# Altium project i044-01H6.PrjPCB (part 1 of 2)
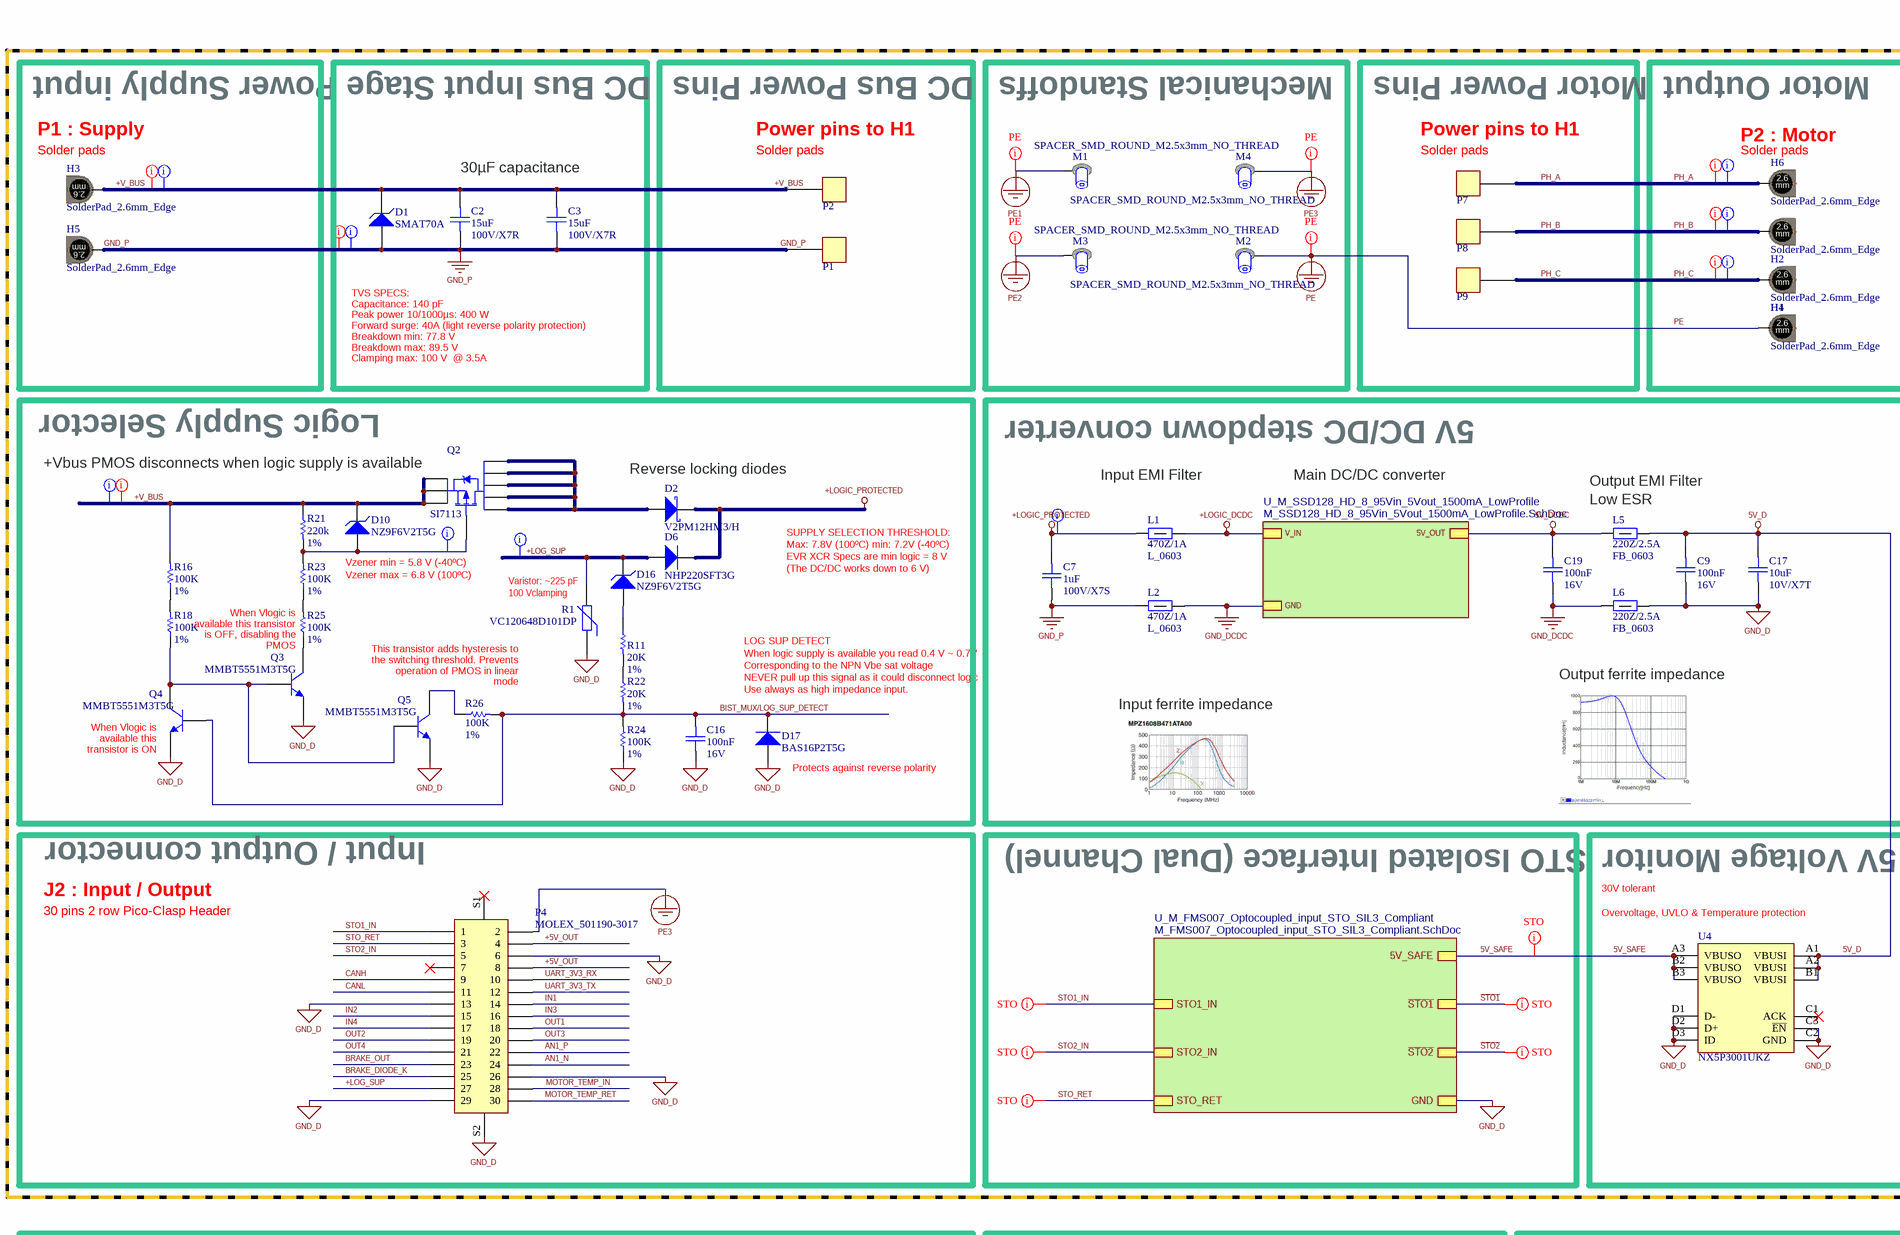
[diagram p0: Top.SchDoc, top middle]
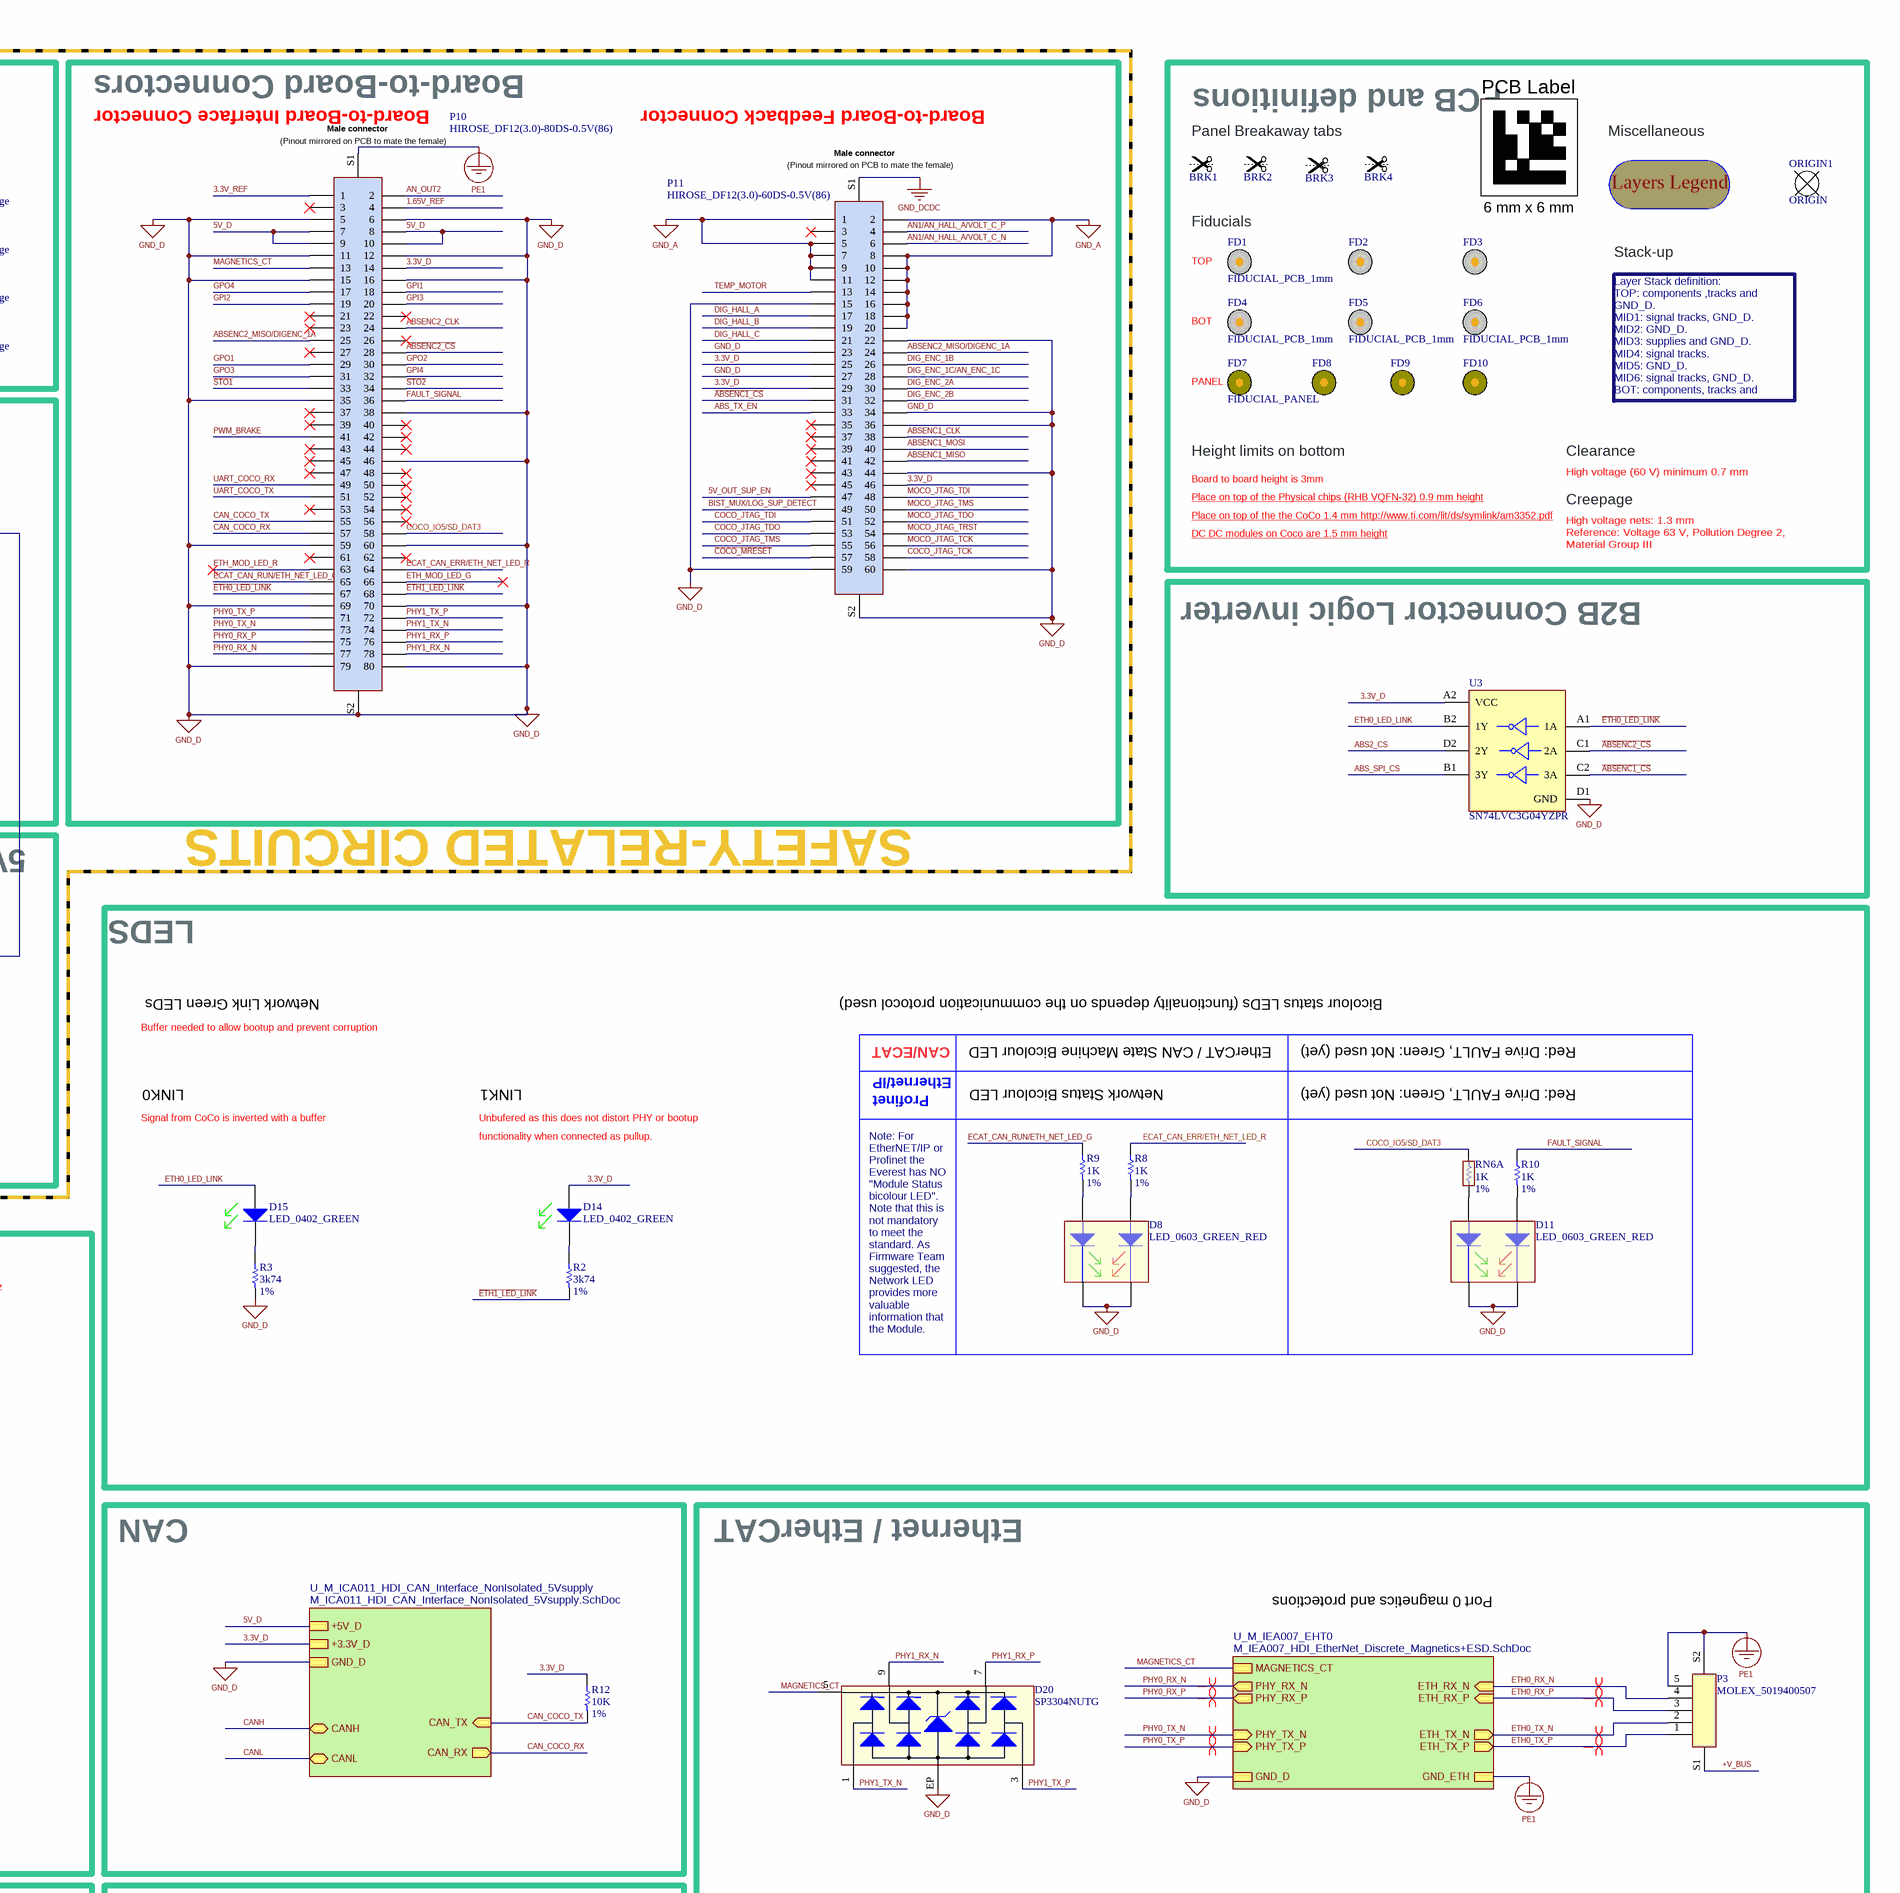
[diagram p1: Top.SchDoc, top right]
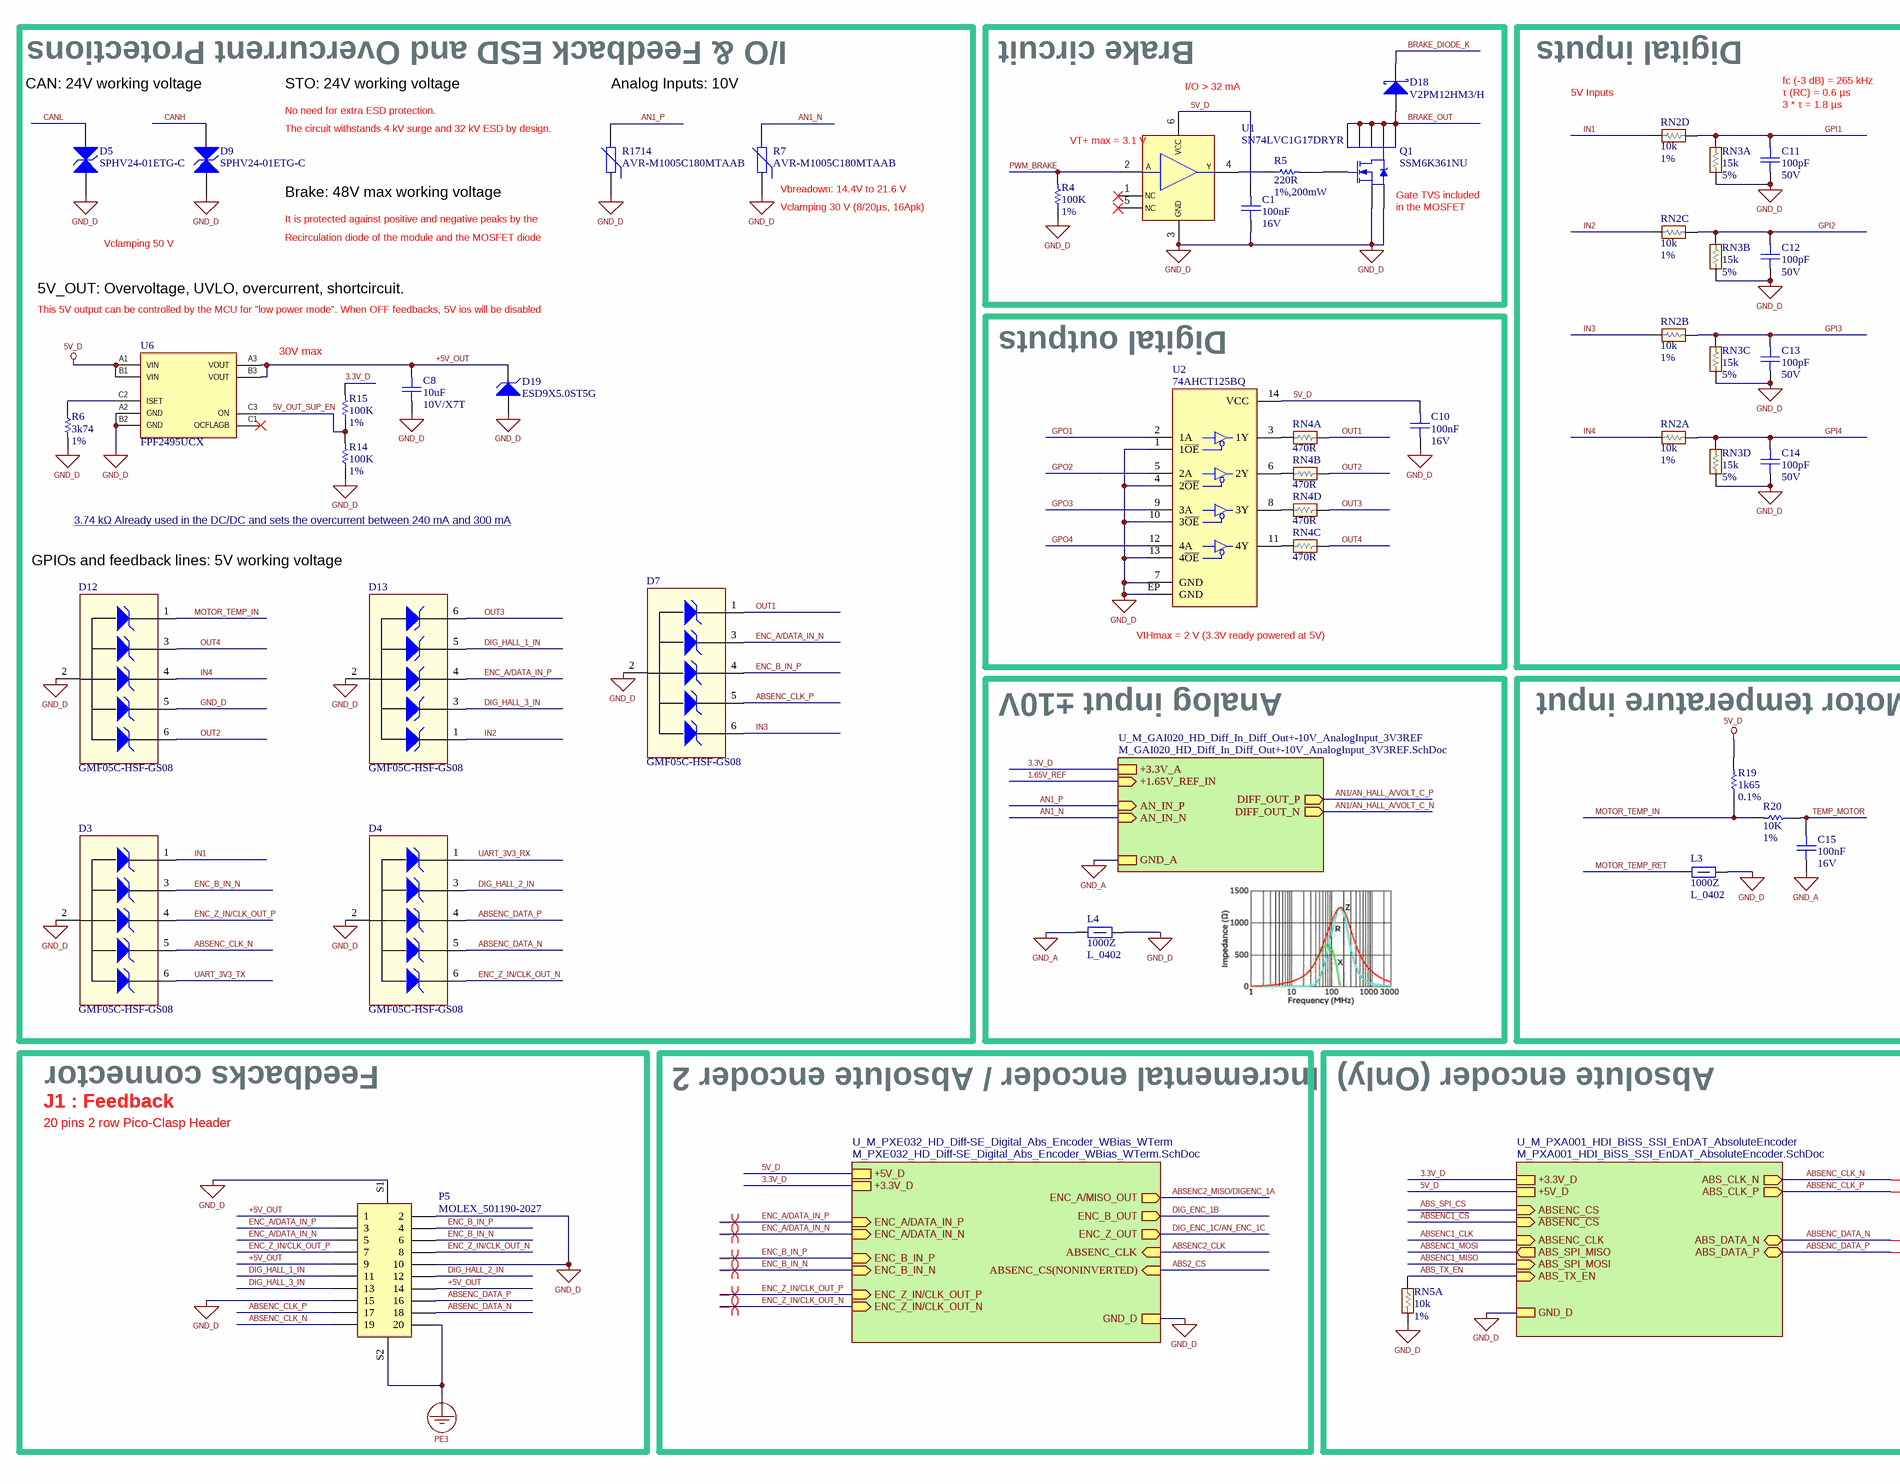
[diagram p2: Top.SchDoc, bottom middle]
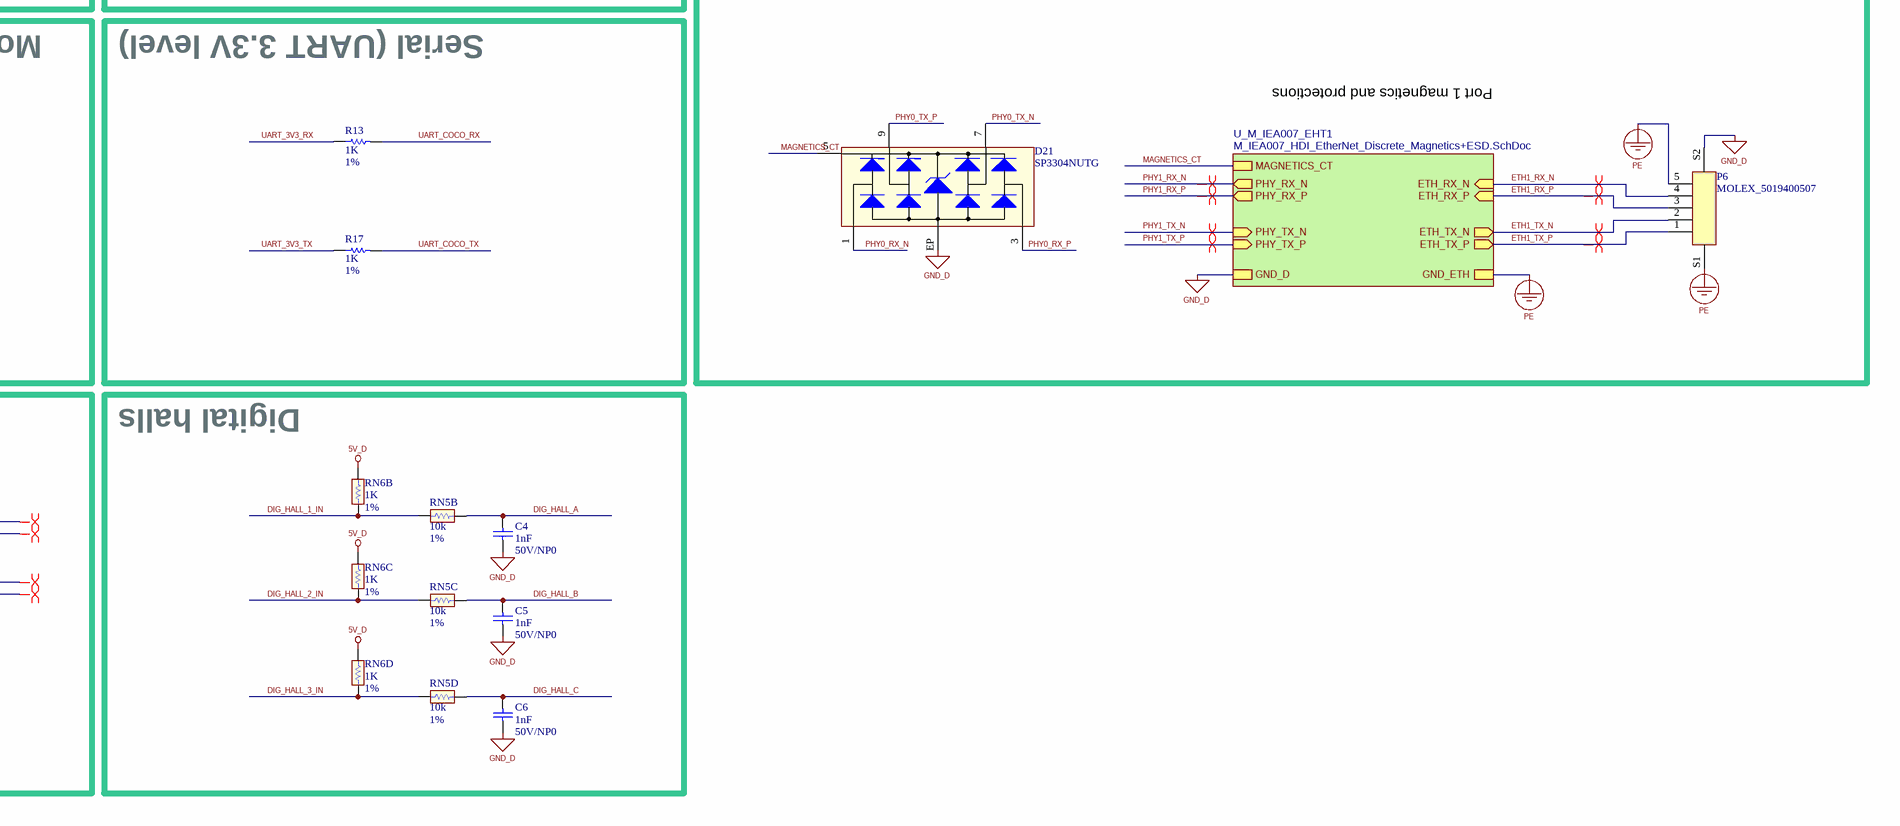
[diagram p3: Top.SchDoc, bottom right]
PCB_Revision: i044-01H6-1.2; ProjectRevision: i044-01H6-1.2.3
8 sheets, 235 parts. Net scope: hierarchical (ports join the sheet entries above them; power ports are global).
Board file: i044-01H6.PcbDoc
Sheets:
  Top.SchDoc
    U_M_SSD128_HD_8_95Vin_5Vout_1500mA_LowProfile = M_SSD128_HD_8_95Vin_5Vout_1500mA_LowProfile.SchDoc
    U_M_ICA011_HDI_CAN_Interface_NonIsolated_5Vsupply = M_ICA011_HDI_CAN_Interface_NonIsolated_5Vsupply.SchDoc
    U_M_PXE032_HD_Diff-SE_Digital_Abs_Encoder_WBias_WTerm = M_PXE032_HD_Diff-SE_Digital_Abs_Encoder_WBias_WTerm.SchDoc
    U_M_IEA007_EHT0 = M_IEA007_HDI_EtherNet_Discrete_Magnetics+ESD.SchDoc
    U_M_IEA007_EHT1 = M_IEA007_HDI_EtherNet_Discrete_Magnetics+ESD.SchDoc
    U_M_PXA001_HDI_BiSS_SSI_EnDAT_AbsoluteEncoder = M_PXA001_HDI_BiSS_SSI_EnDAT_AbsoluteEncoder.SchDoc
    U_M_FMS007_Optocoupled_input_STO_SIL3_Compliant = M_FMS007_Optocoupled_input_STO_SIL3_Compliant.SchDoc
    U_M_GAI020_HD_Diff_In_Diff_Out+-10V_AnalogInput_3V3REF = M_GAI020_HD_Diff_In_Diff_Out+-10V_AnalogInput_3V3REF.SchDoc

## Sheet Top.SchDoc: ixxx
size A1; Organization: Ingenia Drives - Novanta; Address1: Carrer Avila, 124, 2B; Address2: 08018 Barcelona Spain; Address3: www.ingeniamc.com; Address4: www.ingeniamc.com; DocumentNumber: 1; Revision: i044-01H6-1.2.3; SheetNumber: 1; SheetTotal: 8

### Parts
(Parts that share a designator on the sheet are numbered #1, #2 ... from top to bottom, then left to right.)
BRK1  BreakAway_Vias_3mm  [BREAKAWAY_VIAS_3.4MM]  (value not drawn)  (net tie, no BOM)
BRK2  BreakAway_Vias_3mm  [BREAKAWAY_VIAS_3.4MM]  (value not drawn)  (net tie, no BOM)
BRK3  BreakAway_Vias_2mm  [BREAKAWAY_VIAS_2MM]  (value not drawn)  (net tie, no BOM)
BRK4  BreakAway_Vias_3mm  [BREAKAWAY_VIAS_3.4MM]  (value not drawn)  (net tie, no BOM)
C1#1  value 100nF  Voltage: 16V  [C_0402HD]  (hidden comment: C_0402--100nF--16V)
C2#1  value 15uF  Voltage: 100V/X7R  [C_J-LEAD_2STACK_6.1X5.3MM]  (hidden comment: C_2420_2STACK--15uF--100V/X7R)
C3#1  value 15uF  Voltage: 100V/X7R  [C_J-LEAD_2STACK_6.1X5.3MM]  (hidden comment: C_2420_2STACK--15uF--100V/X7R)
C4#1  value 1nF  Voltage: 50V/NP0  [C_0402HD]  (hidden comment: C_0402--1nF--50V/NP0)
C5#1  value 1nF  Voltage: 50V/NP0  [C_0402HD]  (hidden comment: C_0402--1nF--50V/NP0)
C6#1  value 1nF  Voltage: 50V/NP0  [C_0402HD]  (hidden comment: C_0402--1nF--50V/NP0)
C7  value 1uF  Voltage: 100V/X7S  [C_0805]  (hidden comment: C_0805--1uF--100V/X7S)
C8#1  value 10uF  Voltage: 10V/X7T  [C_0603]  (hidden comment: C_0603--10uF--10V/X7T)
C9#1  value 100nF  Voltage: 16V  [C_0402HD]  (hidden comment: C_0402--100nF--16V)
C10  value 100nF  Voltage: 16V  [C_0402HD]  (hidden comment: C_0402--100nF--16V)
C11#1  value 100pF  Voltage: 50V  [C_0402HD]  (hidden comment: C_0402--100pF--50V)
C12  value 100pF  Voltage: 50V  [C_0402HD]  (hidden comment: C_0402--100pF--50V)
C13#1  value 100pF  Voltage: 50V  [C_0402HD]  (hidden comment: C_0402--100pF--50V)
C14#1  value 100pF  Voltage: 50V  [C_0402HD]  (hidden comment: C_0402--100pF--50V)
C15#1  value 100nF  Voltage: 16V  [C_0402HD]  (hidden comment: C_0402--100nF--16V)
C16#1  value 100nF  Voltage: 16V  [C_0402HD]  (hidden comment: C_0402--100nF--16V)
C17#1  value 10uF  Voltage: 10V/X7T  [C_0603]  (hidden comment: C_0603--10uF--10V/X7T)
C19#1  value 100nF  Voltage: 16V  [C_0402HD]  (hidden comment: C_0402--100nF--16V)
D1#1  SMAT70A  [SMA/DO-214AC]
D2  V2PM12HM3/H  [MicroSMP]
D3#1  GMF05C-HSF-GS08  [LLP75-6L]
D4#1  GMF05C-HSF-GS08  [LLP75-6L]
D5#1  SPHV24-01ETG-C  [SOD-882]
D6#1  NHP220SFT3G  [SOD123FL]
D7  GMF05C-HSF-GS08  [LLP75-6L]
D8  LED_0603_GREEN_RED  [LED_0603_DUAL]
D9  SPHV24-01ETG-C  [SOD-882]
D10  NZ9F6V2T5G  [SOD923]
D11  LED_0603_GREEN_RED  [LED_0603_DUAL]
D12  GMF05C-HSF-GS08  [LLP75-6L]
D13  GMF05C-HSF-GS08  [LLP75-6L]
D14  LED_0402_GREEN  [LED_0402]
D15  LED_0402_GREEN  [LED_0402]
D16  NZ9F6V2T5G  [SOD923]
D17  BAS16P2T5G  [SOD923]
D18  V2PM12HM3/H  [MicroSMP]
D19  ESD9X5.0ST5G  [SOD923]
D20  SP3304NUTG  [10-UFDFN]
D21  SP3304NUTG  [10-UFDFN]
FD1  FIDUCIAL_PCB_1mm  [FIDUCIAL_PCB]
FD2  FIDUCIAL_PCB_1mm  [FIDUCIAL_PCB]  (value not drawn)
FD3  FIDUCIAL_PCB_1mm  [FIDUCIAL_PCB]  (value not drawn)
FD4  FIDUCIAL_PCB_1mm  [FIDUCIAL_PCB]
FD5  FIDUCIAL_PCB_1mm  [FIDUCIAL_PCB]
FD6  FIDUCIAL_PCB_1mm  [FIDUCIAL_PCB]
FD7  FIDUCIAL_PANEL  [FIDUCIAL_PANEL]
FD8  FIDUCIAL_PANEL  [FIDUCIAL_PANEL]  (value not drawn)
FD9  FIDUCIAL_PANEL  [FIDUCIAL_PANEL]  (value not drawn)
FD10  FIDUCIAL_PANEL  [FIDUCIAL_PANEL]  (value not drawn)
H1  SolderPad_2.6mm_Edge  [SolderPad_2.6mm_Edge]  (net tie, no BOM)
H2  SolderPad_2.6mm_Edge  [SolderPad_2.6mm_Edge]  (net tie, no BOM)
H3  SolderPad_2.6mm_Edge  [SolderPad_2.6mm_Edge]  (net tie, no BOM)
H4  SolderPad_2.6mm_Edge  [SolderPad_2.6mm_Edge]  (net tie, no BOM)
H5  SolderPad_2.6mm_Edge  [SolderPad_2.6mm_Edge]  (net tie, no BOM)
H6  SolderPad_2.6mm_Edge  [SolderPad_2.6mm_Edge]  (net tie, no BOM)
L1#1  value 470Z/1A  [L_0603]  (hidden comment: L_0603)
L2#1  value 470Z/1A  [L_0603]  (hidden comment: L_0603)
L3  value 1000Z  [L_0402HD]  (hidden comment: L_0402)
L4  value 1000Z  [L_0402HD]  (hidden comment: L_0402)
L5  value 220Z/2.5A  [L_0603]  (hidden comment: FB_0603)
L6  value 220Z/2.5A  [L_0603]  (hidden comment: FB_0603)
LABEL1  LabelPCB  [LABEL_PCB_6X6_AssemblyDrawings]  (value not drawn)  (net tie, no BOM)
LAYERS1  Mark8layersSmall  [Mark8LayersHDI]  (value not drawn)  (net tie, no BOM)
M1  SPACER_SMD_ROUND_M2.5x3mm_NO_THREAD  [WURTH_9774030951R_small]
M2  SPACER_SMD_ROUND_M2.5x3mm_NO_THREAD  [WURTH_9774030951R_small]
M3  SPACER_SMD_ROUND_M2.5x3mm_NO_THREAD  [WURTH_9774030951R_small]
M4  SPACER_SMD_ROUND_M2.5x3mm_NO_THREAD  [WURTH_9774030951R_small]
ORIGIN1  ORIGIN  [ORIGIN]
P1  PAD_1.65mmTH  [PAD_1.65mmTH]  (value not drawn)  (no BOM)
P2  PAD_1.65mmTH  [PAD_1.65mmTH]  (value not drawn)  (no BOM)
P3  MOLEX_5019400507  [MOLEX_5019400507]
P4  MOLEX_501190-3017  [MOLEX_501190-3017]
P5  MOLEX_501190-2027  [MOLEX_501190-2027]
P6  MOLEX_5019400507  [MOLEX_5019400507]
P7  PAD_1.65mmTH  [PAD_1.65mmTH]  (value not drawn)  (no BOM)
P8  PAD_1.65mmTH  [PAD_1.65mmTH]  (value not drawn)  (no BOM)
P9  PAD_1.65mmTH  [PAD_1.65mmTH]  (value not drawn)  (no BOM)
P10  HIROSE_DF12(3.0)-80DS-0.5V(86)  [HIROSE_DF12(3.0)-80DS-0.5V(86)_ROTATED]
P11  HIROSE_DF12(3.0)-60DS-0.5V(86)  [HIROSE_DF12(3.0)-60DS-0.5V(86)]
Q1#1  SSM6K361NU  [6-UDFNB(2x2)]
Q2#1  SI7113  [PowerPAK_1212-8]
Q3  MMBT5551M3T5G  [SOT-723]
Q4  MMBT5551M3T5G  [SOT-723]
Q5  MMBT5551M3T5G  [SOT-723]
R1#1  VC120648D101DP  [R_1206_1MM]
R2#1  value 3k74  Tolerance: 1%  [R_0402HD]  (hidden comment: R_0402--3k74--1%)
R3#1  value 3k74  Tolerance: 1%  [R_0402HD]  (hidden comment: R_0402--3k74--1%)
R4#1  value 100K  Tolerance: 1%  [R_0402HD]  (hidden comment: R_0402--100K--1%)
R5#1  value 220R  Tolerance: 1%,200mW  [R_0402HD]  (hidden comment: R_0402--220R--1%,200mW)
R6#1  value 3k74  Tolerance: 1%  [R_0402HD]  (hidden comment: R_0402--3k74--1%)
R7#1  AVR-M1005C180MTAAB  [R_0402HD]
R8#1  value 1K  Tolerance: 1%  [R_0402HD]  (hidden comment: R_0402--1K--1%)
R9#1  value 1K  Tolerance: 1%  [R_0402HD]  (hidden comment: R_0402--1K--1%)
R10#1  value 1K  Tolerance: 1%  [R_0402HD]  (hidden comment: R_0402--1K--1%)
R11#1  value 20K  Tolerance: 1%  [R_0402HD]  (hidden comment: R_0402--20K--1%)
R12#1  value 10K  Tolerance: 1%  [R_0402HD]  (hidden comment: R_0402--10K--1%)
R13#1  value 1K  Tolerance: 1%  [R_0402HD]  (hidden comment: R_0402--1K--1%)
R14#1  value 100K  Tolerance: 1%  [R_0402HD]  (hidden comment: R_0402--100K--1%)
R15#1  value 100K  Tolerance: 1%  [R_0402HD]  (hidden comment: R_0402--100K--1%)
R16  value 100K  Tolerance: 1%  [R_0402HD]  (hidden comment: R_0402--100K--1%)
R17  value 1K  Tolerance: 1%  [R_0402HD]  (hidden comment: R_0402--1K--1%)
R18  value 100K  Tolerance: 1%  [R_0402HD]  (hidden comment: R_0402--100K--1%)
R19  value 1k65  Tolerance: 0.1%  [R_0402HD]  (hidden comment: R_0402--1k65--0.1%)
R20  value 10K  Tolerance: 1%  [R_0402HD]  (hidden comment: R_0402--10K--1%)
R21  value 220k  Tolerance: 1%  [R_0402HD]  (hidden comment: R_0402--220k--1%)
R22  value 20K  Tolerance: 1%  [R_0402HD]  (hidden comment: R_0402--20K--1%)
R23  value 100K  Tolerance: 1%  [R_0402HD]  (hidden comment: R_0402--100K--1%)
R24  value 100K  Tolerance: 1%  [R_0402HD]  (hidden comment: R_0402--100K--1%)
R25  value 100K  Tolerance: 1%  [R_0402HD]  (hidden comment: R_0402--100K--1%)
R26  value 100K  Tolerance: 1%  [R_0402HD]  (hidden comment: R_0402--100K--1%)
R1714  AVR-M1005C180MTAAB  [R_0402HD]
RN2#1  value 10k  Tolerance: 1%  [R_ARR_CRA04S08]  (hidden comment: R_ARRAY_0804_8--10k--1%)  (parts A,B,C,D of 4)
RN3#1  value 15k  Tolerance: 5%  [R_ARR_CRA04S08]  (hidden comment: R_ARRAY_0804_8--15k--5%)  (parts A,B,C,D of 4)
RN4  value 470R  [R_ARR_0804_8]  (hidden comment: R_ARRAY_0804_8--470R--5%)  (parts A,B,C,D of 4)
RN5  value 10k  Tolerance: 1%  [R_ARR_CRA04S08]  (hidden comment: R_ARRAY_0804_8--10k--1%)  (parts A,B,C,D of 4)
RN6  value 1K  Tolerance: 1%  [R_ARR_CRA04S08]  (hidden comment: R_ARRAY_0804_8--1K--1%)  (parts A,B,C,D of 4)
U1#1  SN74LVC1G17DRYR  [6-SON(1.45x1)]
U2#1  74AHCT125BQ  [DHVQFN14]
U3#1  SN74LVC3G04YZPR  [8-DSBGA]
U4  NX5P3001UKZ  [WLCSP12]
U6  FPF2495UCX  [9-UFBGA]

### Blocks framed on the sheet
Power Supply input: H3 H5
DC Bus Input Stage: C2#1 C3#1 D1#1
DC Bus Power Pins: P1 P2
Mechanical Standoffs: M1-M4
Motor Power Pins: P7-P9
Motor Output: H1 H2 H4 H6
Board-to-Board Connectors: P10 P11
PCB and definitions: BRK1-BRK4 FD1-FD10 LABEL1 LAYERS1 ORIGIN1
Logic Supply Selector: C16#1 D2 D6#1 D10 D16 D17 Q2#1 Q3-Q5 R1#1 R11#1 R16 R18 R21-R26
5V DC/DC stepdown converter: C7 C9#1 C17#1 C19#1 L1#1 L2#1 L5 L6
B2B Connector Logic inverter: U3#1
Input / Output connector: P4
5V Voltage Monitor: U4
LEDS: D8 D11 D14 D15 R2#1 R3#1 R8#1 R9#1 R10#1 RN6
I/O & Feedback ESD and Overcurrent Protections: C8#1 D3#1 D4#1 D5#1 D7 D9 D12 D13 D19 R6#1 R7#1 R14#1 R15#1 R1714 U6
Brake circuit: C1#1 D18 Q1#1 R4#1 R5#1 U1#1
Digital inputs: C11#1 C12 C13#1 C14#1 RN2#1 RN3#1
Digital outputs: C10 RN4 U2#1
CAN: R12#1
Ethernet / EtherCAT: D20 D21 P3 P6
Analog input ±10V: L4
Motor temperature input: C15#1 L3 R19 R20
Serial (UART 3.3V level): R13#1 R17
Feedbacks connector: P5
Absolute encoder (Only): RN5
Digital halls: C4#1 C5#1 C6#1 RN5 RN6

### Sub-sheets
U_M_FMS007_Optocoupled_input_STO_SIL3_Compliant = M_FMS007_Optocoupled_input_STO_SIL3_Compliant.SchDoc: STO1_IN, STO_RET, 5V_SAFE, ~{STO1}, GND, STO2_IN, ~{STO2}
U_M_GAI020_HD_Diff_In_Diff_Out+-10V_AnalogInput_3V3REF = M_GAI020_HD_Diff_In_Diff_Out+-10V_AnalogInput_3V3REF.SchDoc: +3.3V_A, GND_A, AN_IN_P (in), AN_IN_N (in), +1.65V_REF_IN (in), DIFF_OUT_P (out), DIFF_OUT_N (out)
U_M_ICA011_HDI_CAN_Interface_NonIsolated_5Vsupply = M_ICA011_HDI_CAN_Interface_NonIsolated_5Vsupply.SchDoc: CANH (bidir), CANL (bidir), CAN_TX (in), CAN_RX (out), +5V_D, GND_D, +3.3V_D
U_M_IEA007_EHT0 = M_IEA007_HDI_EtherNet_Discrete_Magnetics+ESD.SchDoc: MAGNETICS_CT, GND_D, GND_ETH, ETH_TX_N (out), ETH_TX_P (out), ETH_RX_N (in), ETH_RX_P (in), PHY_TX_N (in), PHY_TX_P (in), PHY_RX_N (out), PHY_RX_P (out)
U_M_IEA007_EHT1 = M_IEA007_HDI_EtherNet_Discrete_Magnetics+ESD.SchDoc: MAGNETICS_CT, GND_D, GND_ETH, ETH_TX_N (out), ETH_TX_P (out), ETH_RX_N (in), ETH_RX_P (in), PHY_TX_N (in), PHY_TX_P (in), PHY_RX_N (out), PHY_RX_P (out)
U_M_PXA001_HDI_BiSS_SSI_EnDAT_AbsoluteEncoder = M_PXA001_HDI_BiSS_SSI_EnDAT_AbsoluteEncoder.SchDoc: GND_D, +3.3V_D, ABS_CLK_N (out), ABS_SPI_MISO (out), ABS_TX_EN (in), ABSENC_CS (in), ABSENC_CLK (in), ABS_CLK_P (out), ABS_DATA_N (bidir), ABS_SPI_MOSI (in), ABS_DATA_P (bidir), +5V_D, ~{ABSENC_CS} (in)
U_M_PXE032_HD_Diff-SE_Digital_Abs_Encoder_WBias_WTerm = M_PXE032_HD_Diff-SE_Digital_Abs_Encoder_WBias_WTerm.SchDoc: +5V_D, +3.3V_D, GND_D, ENC_A/DATA_IN_P (in), ENC_A/MISO_OUT (out), ENC_A/DATA_IN_N (in), ENC_B_IN_P (in), ENC_B_IN_N (in), ENC_Z_IN/CLK_OUT_P (in), ENC_Z_IN/CLK_OUT_N (in), ENC_B_OUT (out), ENC_Z_OUT (out), ABSENC_CLK (in), ABSENC_CS(NONINVERTED) (in)
U_M_SSD128_HD_8_95Vin_5Vout_1500mA_LowProfile = M_SSD128_HD_8_95Vin_5Vout_1500mA_LowProfile.SchDoc: V_IN, GND, 5V_OUT

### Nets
5V_D: C1#1.2 C9#1.2 C10.2 C17#1.2 L5.2 P10.7 P10.8 P10.9 P10.10 R19.2 RN6.4 RN6.6 RN6.8 U1#1.6(VCC) U2#1.14(VCC) U4.A1(VBUSI) U4.A2(VBUSI) U4.B1(VBUSI) U6.A1(VIN) U6.B1(VIN) ; sheet U_M_ICA011_HDI_CAN_Interface_NonIsolated_5Vsupply/+5V_D, sheet U_M_PXE032_HD_Diff-SE_Digital_Abs_Encoder_WBias_WTerm/+5V_D, sheet U_M_PXA001_HDI_BiSS_SSI_EnDAT_AbsoluteEncoder/+5V_D
5V_DCDC: C19#1.2 L5.1 ; sheet U_M_SSD128_HD_8_95Vin_5Vout_1500mA_LowProfile/5V_OUT
+LOGIC_DCDC: L1#1.2 ; sheet U_M_SSD128_HD_8_95Vin_5Vout_1500mA_LowProfile/V_IN
+LOGIC_PROTECTED: C7.2 D2.2(K) D6#1.2(K) L1#1.1
GND_A: C15#1.1 L4.1 P11.1 P11.2 P11.5 P11.7 P11.8 P11.9 P11.10 P11.11 P11.12 P11.14 P11.16 P11.18 P11.20 ; sheet U_M_GAI020_HD_Diff_In_Diff_Out+-10V_AnalogInput_3V3REF/GND_A
GND_D: C1#1.1 C4#1.2 C5#1.2 C6#1.2 C8#1.1 C9#1.1 C10.1 C11#1.2 C12.2 C13#1.2 C14#1.2 C16#1.1 C17#1.1 D3#1.2 D4#1.2 D5#1.2 D7.2 D8.3(K_RED) D8.4(K_GREEN) D9.2 D11.3(K_RED) D11.4(K_GREEN) D12.2 D12.5 D13.2 D17.1(A) D19.1(A) D20.EP(GND) D21.EP(GND) L3.2 L4.2 L6.2 P4.6 P4.13 P4.26 P4.29 P4.S2(SHIELD2) P5.2 P5.10 P5.15 P5.S1(SHIELD2) P6.S2(SHIELD2) P10.5 P10.6 P10.11 P10.12 P10.15 P10.16 P10.35 P10.38 P10.46 P10.59 P10.60 P10.69 P10.70 P10.79 P10.80 P10.S2(Shield2) P11.15 P11.22 P11.23 P11.27 P11.34 P11.36 P11.44 P11.59 P11.60 P11.S2(Shield2) Q1#1.4(S) Q1#1.7(S) Q3.2(E) Q4.2(E) Q5.2(E) R1#1.1 R3#1.2 R4#1.1 R6#1.2 R7#1.1 R14#1.1 R24.1 R1714.1 RN3#1.1 RN3#1.3 RN3#1.5 RN3#1.7 RN5.2 U1#1.3(GND) U2#1.1(1~{OE}) U2#1.4(2~{OE}) U2#1.7(GND) U2#1.10(3~{OE}) U2#1.13(4~{OE}) U2#1.EP(GND) U3#1.D1(GND) U4.C2(GND) U4.C3(~{EN}) U4.D1(D-) U4.D2(D+) U4.D3(ID) U6.A2(GND) U6.B2(GND) ; sheet U_M_ICA011_HDI_CAN_Interface_NonIsolated_5Vsupply/GND_D, sheet U_M_PXE032_HD_Diff-SE_Digital_Abs_Encoder_WBias_WTerm/GND_D, sheet U_M_IEA007_EHT0/GND_D, sheet U_M_IEA007_EHT1/GND_D, sheet U_M_PXA001_HDI_BiSS_SSI_EnDAT_AbsoluteEncoder/GND_D, sheet U_M_FMS007_Optocoupled_input_STO_SIL3_Compliant/GND
GND_DCDC: C19#1.1 L2#1.2 L6.1 P11.S1(shield1) ; sheet U_M_SSD128_HD_8_95Vin_5Vout_1500mA_LowProfile/GND
GND_P: C2#1.2 C3#1.2 C7.1 D1#1.1(A) H5.1 L2#1.1 P1.1
PE: H1.1 M2.1 P6.5 P6.S1(SHIELD1) ; sheet U_M_IEA007_EHT1/GND_ETH
PE1: M1.1 P3.5 P3.S2(SHIELD2) P10.S1(Shield2) ; sheet U_M_IEA007_EHT0/GND_ETH
PE2: M3.1
PE3: M4.1 P4.2 P5.20 P5.S2(SHIELD2)
1.65V_REF: P10.4 ; sheet U_M_GAI020_HD_Diff_In_Diff_Out+-10V_AnalogInput_3V3REF/+1.65V_REF_IN
3.3V_D: D14.1(A) P10.14 P11.25 P11.29 P11.46 R12#1.1 R15#1.2 U3#1.A2(VCC) ; sheet U_M_ICA011_HDI_CAN_Interface_NonIsolated_5Vsupply/+3.3V_D, sheet U_M_PXE032_HD_Diff-SE_Digital_Abs_Encoder_WBias_WTerm/+3.3V_D, sheet U_M_PXA001_HDI_BiSS_SSI_EnDAT_AbsoluteEncoder/+3.3V_D, sheet U_M_GAI020_HD_Diff_In_Diff_Out+-10V_AnalogInput_3V3REF/+3.3V_A
3.3V_REF: P10.1
5V_OUT_SUP_EN: P11.47 R14#1.2 R15#1.1 U6.C3(ON)
5V_SAFE: U4.A3(VBUSO) U4.B2(VBUSO) U4.B3(VBUSO) ; sheet U_M_FMS007_Optocoupled_input_STO_SIL3_Compliant/5V_SAFE
+5V_OUT: C8#1.2 D19.2(K) P4.4 P4.8 P5.1 P5.9 P5.14 U6.A3(VOUT) U6.B3(VOUT)
+LOG_SUP: D6#1.1(A) D16.2(K) P4.27 R1#1.2
+V_BUS: C2#1.1 C3#1.1 D1#1.2(K) D10.2(K) H3.1 P2.1 P3.S1(SHIELD1) Q2#1.1(S1) Q2#1.2(S2) Q2#1.3(S3) R16.2 R21.1
~{ABSENC1_CS}: P11.31 U3#1.C2(3A) ; sheet U_M_PXA001_HDI_BiSS_SSI_EnDAT_AbsoluteEncoder/~{ABSENC_CS}
~{ABSENC2_CS}: P10.28 U3#1.C1(2A)
~{COCO_MRESET}: P11.57
~{ETH0_LED_LINK}: P10.67 U3#1.A1(1A)
~{ETH1_LED_LINK}: P10.68 R2#1.2
~{STO1}: P10.33 ; sheet U_M_FMS007_Optocoupled_input_STO_SIL3_Compliant/~{STO1}
~{STO2}: P10.34 ; sheet U_M_FMS007_Optocoupled_input_STO_SIL3_Compliant/~{STO2}
ABS2_CS: U3#1.D2(2Y) ; sheet U_M_PXE032_HD_Diff-SE_Digital_Abs_Encoder_WBias_WTerm/ABSENC_CS(NONINVERTED)
ABS_SPI_CS: U3#1.B1(3Y) ; sheet U_M_PXA001_HDI_BiSS_SSI_EnDAT_AbsoluteEncoder/ABSENC_CS
ABS_TX_EN: P11.33 RN5.1 ; sheet U_M_PXA001_HDI_BiSS_SSI_EnDAT_AbsoluteEncoder/ABS_TX_EN
ABSENC1_CLK: P11.38 ; sheet U_M_PXA001_HDI_BiSS_SSI_EnDAT_AbsoluteEncoder/ABSENC_CLK
ABSENC1_MISO: P11.42 ; sheet U_M_PXA001_HDI_BiSS_SSI_EnDAT_AbsoluteEncoder/ABS_SPI_MOSI
ABSENC1_MOSI: P11.40 ; sheet U_M_PXA001_HDI_BiSS_SSI_EnDAT_AbsoluteEncoder/ABS_SPI_MISO
ABSENC2_CLK: P10.24 ; sheet U_M_PXE032_HD_Diff-SE_Digital_Abs_Encoder_WBias_WTerm/ABSENC_CLK
ABSENC2_MISO/DIGENC_1A: P10.25 P11.24 ; sheet U_M_PXE032_HD_Diff-SE_Digital_Abs_Encoder_WBias_WTerm/ENC_A/MISO_OUT
ABSENC_CLK_N: D3#1.5 P5.19 ; sheet U_M_PXA001_HDI_BiSS_SSI_EnDAT_AbsoluteEncoder/ABS_CLK_N
ABSENC_CLK_P: D7.5 P5.17 ; sheet U_M_PXA001_HDI_BiSS_SSI_EnDAT_AbsoluteEncoder/ABS_CLK_P
ABSENC_DATA_N: D4#1.5 P5.18 ; sheet U_M_PXA001_HDI_BiSS_SSI_EnDAT_AbsoluteEncoder/ABS_DATA_N
ABSENC_DATA_P: D4#1.4 P5.16 ; sheet U_M_PXA001_HDI_BiSS_SSI_EnDAT_AbsoluteEncoder/ABS_DATA_P
AN1/AN_HALL_A/VOLT_C_N: P11.6 ; sheet U_M_GAI020_HD_Diff_In_Diff_Out+-10V_AnalogInput_3V3REF/DIFF_OUT_N
AN1/AN_HALL_A/VOLT_C_P: P11.4 ; sheet U_M_GAI020_HD_Diff_In_Diff_Out+-10V_AnalogInput_3V3REF/DIFF_OUT_P
AN1_N: P4.24 R7#1.2 ; sheet U_M_GAI020_HD_Diff_In_Diff_Out+-10V_AnalogInput_3V3REF/AN_IN_N
AN1_P: P4.22 R1714.2 ; sheet U_M_GAI020_HD_Diff_In_Diff_Out+-10V_AnalogInput_3V3REF/AN_IN_P
AN_OUT2: P10.2
BIST_MUX/LOG_SUP_DETECT: C16#1.2 D17.2(K) P11.49 Q4.1(B) R22.2 R24.2 R26.2
BRAKE_DIODE_K: D18.2(K) P4.25
BRAKE_OUT: D18.1(A) P4.23 Q1#1.1(D) Q1#1.2(D) Q1#1.5(D) Q1#1.6(D) Q1#1.8(D)
CAN_COCO_RX: P10.57 ; sheet U_M_ICA011_HDI_CAN_Interface_NonIsolated_5Vsupply/CAN_RX
CAN_COCO_TX: P10.55 R12#1.2 ; sheet U_M_ICA011_HDI_CAN_Interface_NonIsolated_5Vsupply/CAN_TX
CANH: D9.1 P4.9 ; sheet U_M_ICA011_HDI_CAN_Interface_NonIsolated_5Vsupply/CANH
CANL: D5#1.1 P4.11 ; sheet U_M_ICA011_HDI_CAN_Interface_NonIsolated_5Vsupply/CANL
COCO_IO5/SD_DAT3: P10.58 RN6.2
COCO_JTAG_TCK: P11.58
COCO_JTAG_TDI: P11.51
COCO_JTAG_TDO: P11.53
COCO_JTAG_TMS: P11.55
DIG_ENC_1B: P11.26 ; sheet U_M_PXE032_HD_Diff-SE_Digital_Abs_Encoder_WBias_WTerm/ENC_B_OUT
DIG_ENC_1C/AN_ENC_1C: P11.28 ; sheet U_M_PXE032_HD_Diff-SE_Digital_Abs_Encoder_WBias_WTerm/ENC_Z_OUT
DIG_ENC_2A: P11.30
DIG_ENC_2B: P11.32
DIG_HALL_1_IN: D13.5 P5.11 RN5.4 RN6.3
DIG_HALL_2_IN: D4#1.3 P5.12 RN5.6 RN6.5
DIG_HALL_3_IN: D13.3 P5.13 RN5.8 RN6.7
DIG_HALL_A: C4#1.1 P11.17 RN5.3
DIG_HALL_B: C5#1.1 P11.19 RN5.5
DIG_HALL_C: C6#1.1 P11.21 RN5.7
ECAT_CAN_ERR/ETH_NET_LED_R: P10.64 R8#1.1
ECAT_CAN_RUN/ETH_NET_LED_G: P10.65 R9#1.1
ENC_A/DATA_IN_N: D7.3 P5.5 ; sheet U_M_PXE032_HD_Diff-SE_Digital_Abs_Encoder_WBias_WTerm/ENC_A/DATA_IN_N
ENC_A/DATA_IN_P: D13.4 P5.3 ; sheet U_M_PXE032_HD_Diff-SE_Digital_Abs_Encoder_WBias_WTerm/ENC_A/DATA_IN_P
ENC_B_IN_N: D3#1.3 P5.6 ; sheet U_M_PXE032_HD_Diff-SE_Digital_Abs_Encoder_WBias_WTerm/ENC_B_IN_N
ENC_B_IN_P: D7.4 P5.4 ; sheet U_M_PXE032_HD_Diff-SE_Digital_Abs_Encoder_WBias_WTerm/ENC_B_IN_P
ENC_Z_IN/CLK_OUT_N: D4#1.6 P5.8 ; sheet U_M_PXE032_HD_Diff-SE_Digital_Abs_Encoder_WBias_WTerm/ENC_Z_IN/CLK_OUT_N
ENC_Z_IN/CLK_OUT_P: D3#1.4 P5.7 ; sheet U_M_PXE032_HD_Diff-SE_Digital_Abs_Encoder_WBias_WTerm/ENC_Z_IN/CLK_OUT_P
ETH0_LED_LINK: D15.1(A) U3#1.B2(1Y)
ETH0_RX_N: P3.4 ; sheet U_M_IEA007_EHT0/ETH_RX_N
ETH0_RX_P: P3.3 ; sheet U_M_IEA007_EHT0/ETH_RX_P
ETH0_TX_N: P3.2 ; sheet U_M_IEA007_EHT0/ETH_TX_N
ETH0_TX_P: P3.1 ; sheet U_M_IEA007_EHT0/ETH_TX_P
ETH1_RX_N: P6.4 ; sheet U_M_IEA007_EHT1/ETH_RX_N
ETH1_RX_P: P6.3 ; sheet U_M_IEA007_EHT1/ETH_RX_P
ETH1_TX_N: P6.2 ; sheet U_M_IEA007_EHT1/ETH_TX_N
ETH1_TX_P: P6.1 ; sheet U_M_IEA007_EHT1/ETH_TX_P
ETH_MOD_LED_G: P10.66
ETH_MOD_LED_R: P10.63
FAULT_SIGNAL: P10.36 R10#1.1
GPI1: C11#1.1 P10.18 RN2#1.8 RN3#1.2
GPI2: C12.1 P10.19 RN2#1.6 RN3#1.4
GPI3: C13#1.1 P10.20 RN2#1.4 RN3#1.6
GPI4: C14#1.1 P10.32 RN2#1.2 RN3#1.8
GPO1: P10.29 U2#1.2(1A)
GPO2: P10.30 U2#1.5(2A)
GPO3: P10.31 U2#1.9(3A)
GPO4: P10.17 U2#1.12(4A)
IN1: D3#1.1 P4.14 RN2#1.7
IN2: D13.1 P4.15 RN2#1.5
IN3: D7.6 P4.16 RN2#1.3
IN4: D12.4 P4.17 RN2#1.1
MAGNETICS_CT: D20.5(VCC) D21.5(VCC) P10.13 ; sheet U_M_IEA007_EHT0/MAGNETICS_CT, sheet U_M_IEA007_EHT1/MAGNETICS_CT
MOCO_JTAG_TCK: P11.56
MOCO_JTAG_TDI: P11.48
MOCO_JTAG_TDO: P11.52
MOCO_JTAG_TMS: P11.50
MOCO_JTAG_TRST: P11.54
MOTOR_TEMP_IN: D12.1 P4.28 R19.1 R20.2
MOTOR_TEMP_RET: L3.1 P4.30
OUT1: D7.1 P4.18 RN4.1
OUT2: D12.6 P4.19 RN4.3
OUT3: D13.6 P4.20 RN4.7
OUT4: D12.3 P4.21 RN4.5
PH_A: H6.1 P7.1
PH_B: H4.1 P8.1
PH_C: H2.1 P9.1
PHY0_RX_N: D21.1 P10.77 ; sheet U_M_IEA007_EHT0/PHY_RX_N
PHY0_RX_P: D21.3 P10.75 ; sheet U_M_IEA007_EHT0/PHY_RX_P
PHY0_TX_N: D21.7 P10.73 ; sheet U_M_IEA007_EHT0/PHY_TX_N
PHY0_TX_P: D21.9 P10.71 ; sheet U_M_IEA007_EHT0/PHY_TX_P
PHY1_RX_N: D20.9 P10.78 ; sheet U_M_IEA007_EHT1/PHY_RX_N
PHY1_RX_P: D20.7 P10.76 ; sheet U_M_IEA007_EHT1/PHY_RX_P
PHY1_TX_N: D20.1 P10.74 ; sheet U_M_IEA007_EHT1/PHY_TX_N
PHY1_TX_P: D20.3 P10.72 ; sheet U_M_IEA007_EHT1/PHY_TX_P
PWM_BRAKE: P10.41 R4#1.2 U1#1.2(A)
STO1_IN: P4.1 ; sheet U_M_FMS007_Optocoupled_input_STO_SIL3_Compliant/STO1_IN
STO2_IN: P4.5 ; sheet U_M_FMS007_Optocoupled_input_STO_SIL3_Compliant/STO2_IN
STO_RET: P4.3 ; sheet U_M_FMS007_Optocoupled_input_STO_SIL3_Compliant/STO_RET
TEMP_MOTOR: C15#1.2 P11.13 R20.1
UART_3V3_RX: D4#1.1 P4.10 R13#1.1
UART_3V3_TX: D3#1.6 P4.12 R17.1
UART_COCO_RX: P10.49 R13#1.2
UART_COCO_TX: P10.51 R17.2
NetD2_1: D2.1(A) Q2#1.5(D1) Q2#1.6(D2) Q2#1.7(D3) Q2#1.8(D4) Q2#1.9(EP)
NetD8_1: D8.1(GREEN_A) R9#1.2
NetD8_2: D8.2(RED_A) R8#1.2
NetD10_1: D10.1(A) Q2#1.4(G) R21.2 R23.2
NetD11_1: D11.1(GREEN_A) RN6.1
NetD11_2: D11.2(RED_A) R10#1.2
NetD14_2: D14.2(K) R2#1.1
NetD15_2: D15.2(K) R3#1.1
NetD16_1: D16.1(A) R11#1.1
NetQ1#1_3: Q1#1.3(G) R5#1.2
NetQ3_1: Q3.1(B) Q4.3(C) Q5.1(B) R18.1
NetQ3_3: Q3.3(C) R25.1
NetQ5_3: Q5.3(C) R26.1
NetR5#1_1: R5#1.1 U1#1.4(Y)
NetR6#1_1: R6#1.1 U6.C2(ISET)
NetR11#1_2: R11#1.2 R22.1
NetR16_1: R16.1 R18.2
NetR23_1: R23.1 R25.2
NetRN4_2: RN4.2 U2#1.3(1Y)
NetRN4_4: RN4.4 U2#1.6(2Y)
NetRN4_6: RN4.6 U2#1.11(4Y)
NetRN4_8: RN4.8 U2#1.8(3Y)

Not connected (* = marked no-connect by the designer): D20 2(NC) 4(NC) 6(NC) 8(NC) 10(NC); D21 2(NC) 4(NC) 6(NC) 8(NC) 10(NC); P4 7* S1(SHIELD1)*; P10 3* 21* 22* 23* 26* 27* 37* 39* 40* 42* 43* 44* 45* 47* 48* 50* 52* 53* 54* 56* 61* 62*; P11 3* 35* 37* 39* 41* 43* 45*; U1#1 1(NC)* 5(NC)*; U4 C1(ACK)*; U6 C1(OCFLAGB)*

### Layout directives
net class ProtectiveEarth: PE, PE1, PE2, PE3
net class HighVoltage: +LOG_SUP, +LOGIC_PROTECTED, +V_BUS, GND_P, PH_A, PH_B, PH_C
net class HighCurrent: +V_BUS, GND_P, PH_A, PH_B, PH_C
differential pair: ABSENC_CLK_N, ABSENC_CLK_P, ABSENC_DATA_N, ABSENC_DATA_P, ENC_A/DATA_IN_N, ENC_A/DATA_IN_P, ENC_B_IN_N, ENC_B_IN_P, ENC_Z_IN/CLK_OUT_N, ENC_Z_IN/CLK_OUT_P, ETH0_RX_N, ETH0_RX_P, ETH0_TX_N, ETH0_TX_P, ETH1_RX_N, ETH1_RX_P, ETH1_TX_N, ETH1_TX_P, PHY0_RX_N, PHY0_RX_P, PHY0_TX_N, PHY0_TX_P, PHY1_RX_N, PHY1_RX_P, PHY1_TX_N, PHY1_TX_P
net class STO: 5V_SAFE, STO1_IN, STO2_IN, STO_RET, ~{STO1}, ~{STO2}
net class HighVoltageFloating: NetD10_1

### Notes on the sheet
- P1 : Supply
- Power pins to H1
- (near P7) Power pins to H1
- (near H6) P2 : Motor
- Board-to-Board Interface Connector
- Board-to-Board Feedback Connector
- Panel Breakaway tabs
- Miscellaneous
- (near H3) Solder pads
- 30µF capacitance
- (near P2) Solder pads
- (near P7) Solder pads
- (near H6) Solder pads
- (near FD1) TOP
- (near FD1) Fiducials
- Stack-up
- (near FD4) BOT
- TVS SPECS:
  Capacitance: 140 pF
  Peak power 10/1000µs: 400 W
  Forward surge: 40A (light reverse polarity protection)
  Breakdown min: 77.8 V
  Breakdown max: 89.5 V
  Clamping max: 100 V  @ 3.5A
- (near FD7) PANEL
- Layer Stack definition:
  TOP: components ,tracks and GND_D.
  MID1: signal tracks, GND_D.
  MID2: GND_D.
  MID3: supplies and GND_D.
  MID4: signal tracks.
  MID5: GND_D.
  MID6: signal tracks, GND_D.
  BOT: components, tracks and GND_D.
- (near Q2#1) +Vbus PMOS disconnects when logic supply is available
- (near D2) Reverse locking diodes
- Input EMI Filter
- Main DC/DC converter
- Output EMI Filter
- (near L5) Low ESR
- Place on top of the Physical chips (RHB VQFN-32) 0.9 mm height <http://www.ti.com/lit/ml/mpqf130c/mpqf130c.pdf>
- Height limits on bottom
- Board to board height is 3mm
- Creepage
- Clearance
- High voltage (60 V) minimum 0.7 mm
- (near D10) Vzener min = 5.8 V (-40ºC)
- SUPPLY SELECTION THRESHOLD:
- Max: 7.8V (100ºC) min: 7.2V (-40ºC)
- EVR XCR Specs are min logic = 8 V
- (The DC/DC works down to 6 V)
- Place on top of the the CoCo 1.4 mm http://www.ti.com/lit/ds/symlink/am3352.pdf <http://www.ti.com/lit/ml/mpqf130c/mpqf130c.pdf>
- DC DC modules on Coco are 1.5 mm height <http://www.ti.com/lit/ml/mpqf130c/mpqf130c.pdf>
- High voltage nets: 1.3 mm
- Reference: Voltage 63 V, Pollution Degree 2,
- Material Group III
- Vzener max = 6.8 V (100ºC)
- (near R1#1) Varistor: |25 pF
- (near R1#1) 100 Vclamping
- When Vlogic is available this transistor is OFF, disabling the PMOS
- This transistor adds hysteresis to the switching threshold. Prevents operation of PMOS in linear mode
- LOG SUP DETECT
- When logic supply is available you read 0.4 V ~ 0.7V
- Corresponding to the NPN Vbe sat voltage
- NEVER pull up this signal as it could disconnect logic
- Use always as high impedance input.
- Output ferrite impedance
- Input ferrite impedance
- (near Q4) When Vlogic is available this transistor is ON
- (near D17) Protects against reverse polarity
- STO Isolated Interface (Dual Channel)
- SAFETY-RELATED CIRCUITS
- J2 : Input / Output
- 30 pins 2 row Pico-Clasp Header
- (near U4) Overvoltage, UVLO & Temperature protection
- 30V tolerant
- Buffer needed to allow bootup and prevent corruption
- Network Link Green LEDs
- Bicolour status LEDs (functionality depends on the communication protocol used)
- CAN/ECAT
- EtherCAT / CAN State Machine Bicolour LED
- Red: Drive FAULT, Green: Not used (yet)
- LINK0
- LINK1
- Ethernet/IP
- Profinet
- Network Status Bicolour LED
- Signal from CoCo is inverted with a buffer
- Unbufered as this does not distort PHY or bootup
- functionality when connected as pullup.
- CAN: 24V working voltage
- STO: 24V working voltage
- Analog Inputs: 10V
- (near U1#1) I/O > 32 mA
- fc (-3 dB) = 265 kHz
- No need for extra ESD protection.
- (near R1714) The circuit withstands 4 kV surge and 32 kV ESD by design.
- (near U1#1) VT+ max = 3.1 V
- 5V Inputs
- τ (RC) = 0.6 µs
- (near C11#1) 3 * τ = 1.8 µs
- Note: For EtherNET/IP or Profinet the Everest has NO "Module Status bicolour LED".
  Note that this is not mandatory to meet the standard. As Firmware Team suggested, the Network LED provides more valuable information that the Module.
- Brake: 48V max working voltage
- (near R7#1) Vbreadown: 14.4V to 21.6 V
- (near R7#1) Vclamping 30 V (8/20µs, 16Apk)
- (near Q1#1) Gate TVS included
- (near Q1#1) in the MOSFET
- Vclamping 50 V
- It is protected against positive and negative peaks by the
- Recirculation diode of the module and the MOSFET diode
- 5V_OUT: Overvoltage, UVLO, overcurrent, shortcircuit.
- This 5V output can be controlled by the MCU for "low power mode". When OFF feedbacks, 5V ios will be disabled
- 30V max
- Port 0 magnetics and protections
- GPIOs and feedback lines: 5V working voltage
- 3.74 kΩ Already used in the DC/DC and sets the overcurrent between 240 mA and 300 mA <https://docs.google.com/spreadsheets/d/1f01-czJ9mk4RUmEfMIF1fFCiRUs7E1iqmfBdWU4qd7A/edit?usp=sharing>
- (near U2#1) VIHmax = 2 V (3.3V ready powered at 5V)
- Port 1 magnetics and protections
- Incremental encoder / Absolute encoder 2
- J1 : Feedback
- 20 pins 2 row Pico-Clasp Header

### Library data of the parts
BRK1 BRK2 BRK4 = BreakAway_Vias_3mm: 3.4 mm break away vias; TemperatureMaxC: 0
BRK3 = BreakAway_Vias_2mm: Small 2 mm break away holes (ONLY WHEN SPACE IS LIMITTED); TemperatureMaxC: 200; TemperatureMinC: -60
C1#1 C9#1 C10 C15#1 C16#1 C19#1 = C_0402[[/\]]100nF[[/\]]16V: CAP CER 100nF 16V X7R 0402; Part Number: C_0402; ManufacturerName: Murata; ManufacturerPN: GRM155R71C104KA88D; AlternativeManufacturer: Wurth; IsPreferred: 0; IngeniaID: 672; IsGeneric: 1; AlternativePN: 885012205037; TemperatureMaxC: 125; TemperatureMinC: -55
C2#1 C3#1 = C_2420_2STACK[[/\]]15uF[[/\]]100V/X7R: 15µF 100V Ceramic Capacitor X7R Stacked SMD, 2 J-Lead (6.10mm x 5.30mm); ManufacturerName: Murata; ManufacturerPN: KRM55WR72A156MH01K; AlternativeManufacturer: TDK Corporation; IsPreferred: 0; IsGeneric: 1; IngeniaID: 4194; TemperatureMaxC: 125; TemperatureMinC: -55; AlternativePN: CKG57KX7S2A156M335JH
C4#1 C5#1 C6#1 = C_0402[[/\]]1nF[[/\]]50V/NP0: MLCC, 0402, NP0, 50V, 1NF, 5%; Part Number: C_0402; ManufacturerName: TDK; ManufacturerPN: C1005NP01H102J050BA; AlternativeManufacturer: Murata; IsPreferred: 0; IsGeneric: 1; IngeniaID: 1899; AlternativePN: GRM1555C1H102GA01D; MTBF55h: 59960233; TemperatureMaxC: 125; TemperatureMinC: -55
C7 = C_0805[[/\]]1uF[[/\]]100V/X7S: MLCC, 1uF 100V X7S Boardflex 1.45mm height; ManufacturerName: TDK Corporation; ManufacturerPN: C2012X7S2A105K125AE; IsPreferred: 1; IngeniaID: 2972; InternalStock: 0; TemperatureMaxC: 125; TemperatureMinC: -55; MTBF55h: 28045508; AlternativePN: C2012X7S2A105M125AE
C8#1 = C_0603[[/\]]10uF[[/\]]10V/X7T: CAP CER 10uF 10V X7T 0603 0.8mm MAX height; ManufacturerName: Murata; ManufacturerPN: GRM188D71A106MA73D; AlternativeManufacturer: Murata Electronics North America; IsPreferred: 0; IngeniaID: 2978; TemperatureMaxC: 125; TemperatureMinC: -55; MTBF55h: 21770245; AlternativePN: GRM188D71A106KA73D
C11#1 C12 C13#1 C14#1 = C_0402[[/\]]100pF[[/\]]50V: CAP CER 100pF 50V NP0/C0G 0402; Part Number: C_0402; ManufacturerName: Yageo; ManufacturerPN: CC0402JRNPO9BN101; AlternativeManufacturer: Kemet; IsPreferred: 0; IsGeneric: 1; IngeniaID: 1451; TemperatureMaxC: 125; TemperatureMinC: -55; MTBF55h: 77243743; AlternativePN: C0402H101J5GAFT1K0; AdditionalInformation: NP0
C17#1 = C_0603[[/\]]10uF[[/\]]10V/X7T: CAP CER 10uF 10V X7T 0603 0.8mm MAX height; ManufacturerName: Murata; ManufacturerPN: GRM188D71A106MA73D; AlternativeManufacturer: Murata Electronics North America; IsPreferred: 0; IngeniaID: 2978; AlternativePN: GRM188D71A106KA73D; MTBF55h: 21770245; TemperatureMaxC: 125; TemperatureMinC: -55
D1#1 = SMAT70A: DIODE TVS 70V 400W Unidirectional 100V Clamping; ManufacturerName: Diodes Inc.; ManufacturerPN: SMAT70A-13-F; Value: TVS 70V; IsPreferred: 1; IsGeneric: 0; IngeniaID: 857; TemperatureMaxC: 150; TemperatureMinC: -55
D2 D18 = V2PM12HM3/H: DIODE SCHOTTKY 120V 2A MICROSMP; ManufacturerName: Vishay; IsPreferred: 0; IngeniaID: 4196; TemperatureMaxC: 175; TemperatureMinC: -40; AlternativePN: V2PM12-M3/H
D3#1 D4#1 D7 D12 D13 = GMF05C-HSF-GS08: DIODE TVS 5 channel unidirectional 5V working 12.5V clamping; ManufacturerName: Vishay; Value: TVS 5x5V; IsPreferred: 1; IsGeneric: 0; IngeniaID: 4266; TemperatureMaxC: 125; TemperatureMinC: -55
D5#1 D9 = SPHV24-01ETG-C: TVS Diode Bidirectional 24V working, 50V clamping,3A (8/20µs), 200W pk; ManufacturerName: Littelfuse; AlternativeManufacturer: Littlefuse; Value: TVS 24V; IsPreferred: 0; IngeniaID: 4274; TemperatureMaxC: 125; TemperatureMinC: -40; AlternativePN: AQHV24-01ETG-C
D6#1 = NHP220SFT3G: Diode Standard 200V 2A Low Leakage SOD-123FL; ManufacturerName: ON Semiconductor; IsPreferred: 1; IsGeneric: 0; IngeniaID: 4544; TemperatureMaxC: 175; TemperatureMinC: -65; AlternativePN: NRVHP220SFT3G
D8 D11 = LED_0603_GREEN_RED: GREEN and RED LED vertical; ManufacturerName: Broadcom Limited; ManufacturerPN: HSMF-C165; IsPreferred: 0; IngeniaID: 2959; TemperatureMaxC: 85; TemperatureMinC: -40
D10 D16 = NZ9F6V2T5G: Zener Diode 6.2V 60ohm SOD-923; AlternativeManufacturer: ON Semiconductor; AlternativePN: NZ9F6V2ST5G; IngeniaID: 4424; InternalStock: 0; TemperatureMaxC: 150; TemperatureMinC: -65
D14 D15 = LED_0402_GREEN: GREEN LED CLEAR LENS 2.1Vf 120º Angle 0402; ManufacturerName: Kingbright; ManufacturerPN: APHHS1005CGCK; AlternativeManufacturer: SunLED; IsPreferred: 1; IsGeneric: 0; IngeniaID: 682; TemperatureMaxC: 85; TemperatureMinC: -40; AlternativePN: XZVG68W-2
D17 = BAS16P2T5G: Diode High Speed 100V 200mA SOD923; ManufacturerName: ON Semiconductor; AlternativeManufacturer: Central Semiconductor Corp; IsPreferred: 1; IsGeneric: 0; IngeniaID: 4326; TemperatureMaxC: 150; TemperatureMinC: -55; AlternativePN: CMAD4448 TR
D19 = ESD9X5.0ST5G: TVS diode 5V 6.2V breakdown min 12Vclamping 9A(8/20us); ManufacturerName: ON Semiconductor; IsPreferred: 0; IngeniaID: 4629; TemperatureMaxC: 150; TemperatureMinC: -65; AlternativePN: SZESD9X5.0ST5G
D20 D21 = SP3304NUTG: Steering/TVS diode 4x array 3.3V, 20A(8/20us) 300W, low capacitance (Ethernet); ManufacturerName: Littlefuse; AlternativeManufacturer: Bourns; Value: TVS 4x3.3V; IsPreferred: 0; IngeniaID: 4267; TemperatureMaxC: 125; TemperatureMinC: -40; AlternativePN: CDDFN10-3304N
FD1-FD6 = FIDUCIAL_PCB_1mm: Single layer fiducial point for the PCB. 1 mm copper diameter 3 mm total diameter.; IsPreferred: True; IngeniaID: 1107; InternalStock: 0; TemperatureMaxC: 200; TemperatureMinC: -65; MTBF55h: 1E20; AdditionalInformation: Fiducial - not a component
FD7-FD10 = FIDUCIAL_PANEL: Double layer fiducial point for the panel; IsPreferred: True; IngeniaID: 1108; InternalStock: 0; TemperatureMaxC: 200; TemperatureMinC: -60; MTBF55h: 1E20; AdditionalInformation: Fiducial - not a component
H1-H6 = Solderpad_2.6mm_Edge: plated hole for edge of the board, 2.6 mm diameter for soldering cables up to 10 AWG; TemperatureMaxC: -55; TemperatureMinC: 200
L1#1 L2#1 = L_0603[[/\]]470Z/1A: Ferrite Bead 470ohm 100MHz, 1A 150mOhm; ManufacturerName: TDK; ManufacturerPN: MPZ1608B471ATA00; CompletePN: L_0603--470Z/1A; IsPreferred: 1; IsGeneric: 0; IngeniaID: 764; TemperatureMaxC: 125; TemperatureMinC: -55; AlternativePN: MPZ1608S471ATA00
L3 L4 = L_0402[[/\]]1000Z: FERRITE BEAD, 0402 CASE, 200mA, Wideband; ManufacturerName: TDK; ManufacturerPN: MMZ1005S102CT000; AlternativeManufacturer: Murata; CompletePN: L_0402--1000Z; IsPreferred: 0; IsGeneric: 1; IngeniaID: 3897; TemperatureMaxC: 125; TemperatureMinC: -55; AlternativePN: BLM15BD102SN1D
L5 L6 = FB_0603[[/\]]220Z/2.5A: Ferrite Bead 220Ohm@100MHz 2.5A DC, 40mOhm, -55ºC ~ 125ºC 0603; ManufacturerName: Murata; ManufacturerPN: BLM18SG221TN1D; CompletePN: FB_0603--220Z/2.5A; IsPreferred: 1; IsGeneric: 0; IngeniaID: 4428; TemperatureMaxC: 125; TemperatureMinC: -55
LABEL1 = LabelPCB: Space for PCB Label on silkscreen (preferred) or Assembly layer only; ManufacturerName: IngeniaLabels; ManufacturerPN: 25; TemperatureMaxC: 200; TemperatureMinC: -65; IngeniaID: 4105; InternalStock: 0
LAYERS1 = Mark8layersSmall: 8 layers stackup legend small
M1-M4 = SPACER_SMD_ROUND_M2.5x3mm_NO_THREAD: Round SMD standoff M2.5 3mm height No Threaded Steel; ManufacturerName: Wurth Electronics Inc; ManufacturerPN: 9774030951R; IsPreferred: 0; IngeniaID: 4248; TemperatureMaxC: 200; TemperatureMinC: -40
ORIGIN1 = ORIGIN: Origin of coordinate axes for pick and place; IsPreferred: True; IngeniaID: 1109; InternalStock: 0; TemperatureMaxC: 200; TemperatureMinC: -60; MTBF55h: 1E20
P1 P2 P7-P9 = PAD_1.65mmTH: 1.65mm hole TH PAD
P3 P6 = MOLEX_5019400507: Male shrouded header, SM, 5 ways vertical, 1 mm pitch; ManufacturerName: Molex; IsPreferred: 0; IngeniaID: 4205; TemperatureMaxC: 105; TemperatureMinC: -40; AlternativePN: 501940-0507
P4 = MOLEX_501190-3017: Male shrouded header, SM, 15x2 ways vertical, 1 mm pitch; ManufacturerName: Molex; IsPreferred: 0; IngeniaID: 4145; TemperatureMaxC: 105; TemperatureMinC: -40; AdditionalInformation: The alternative is supplied without SMD kapton COVER TAPE; AlternativePN: 501190-3027
P5 = MOLEX_501190-2027: Male shrouded header, SM, 20 ways vertical, 1 mm pitch; ManufacturerName: Molex; ManufacturerPN: 5011902027; IsPreferred: 1; IsGeneric: 0; IngeniaID: 4204; TemperatureMaxC: 105; TemperatureMinC: -40
P10 = HIROSE_DF12(3.0)-80DS-0.5V(86): Connector SMD Mezzanine, 80 ways, 0.5mm pitch, 3mm stack height. Male with metal fitting and boss; ManufacturerName: Hirose; IsPreferred: 1; IsGeneric: 0; IngeniaID: 3721; TemperatureMaxC: 125; TemperatureMinC: -45; MTBF55h: 176336644
P11 = HIROSE_DF12(3.0)-60DS-0.5V(86): Connector SMD Mezzanine, 60 ways, 0.5mm pitch, 3mm stack height. Male; ManufacturerName: Hirose; IsPreferred: 0; IngeniaID: 3207; TemperatureMaxC: 125; TemperatureMinC: -45
Q1#1 = SSM6K361NU: MOSFET N-CH 100V, 3.5A 6-UDFNB, 2X2 2.5Vgs th; ManufacturerName: Toshiba; ManufacturerPN: SSM6K361NU,LF; AlternativeManufacturer: ON Semiconductor; IsPreferred: 1; IngeniaID: 4423; InternalStock: 0; TemperatureMaxC: 150; TemperatureMinC: -55; AlternativePN: FDMA86151L
Q2#1 = SI7113: P-Channel MOSFET 100V 10.8A(25C Tc) PowerPAK 1212-8; ManufacturerName: Vishay; ManufacturerPN: SI7113DN-T1-GE3; IsPreferred: 1; IsGeneric: 0; IngeniaID: 4425; TemperatureMaxC: 150; TemperatureMinC: -55; AlternativePN: SI7113DN-T1-E3
Q3-Q5 = MMBT5551M3T5G: Transistor NPN 160V 60mA SOT-723; ManufacturerName: On Semiconductor; IsPreferred: 1; IsGeneric: 0; IngeniaID: 4627; TemperatureMaxC: 150; TemperatureMinC: -55
R1#1 = VC120648D101DP: Varistor SMD 1206 100A 48VDC working 62Vtyp, clamping 100Vc 100A; ManufacturerName: AVX Corporation; AlternativeManufacturer: Littelfuse; IsPreferred: 1; IngeniaID: 4198; InternalStock: 0; TemperatureMaxC: 125; TemperatureMinC: -55; AlternativePN: V48MLA1206NH
R2#1 R3#1 R6#1 = R_0402[[/\]]3k74[[/\]]1%: Resistor 0402 3k74 1%, 0.063W; Part Number: R_0402; ManufacturerName: Vishay Dale; ManufacturerPN: CRCW04023K74FKED; AlternativeManufacturer: Yageo; IsPreferred: 0; IsGeneric: 1; IngeniaID: 2330; TemperatureMaxC: 155; TemperatureMinC: -55; AlternativePN: RC0402FR-073K74L
R4#1 R14#1 R15#1 R16 R18 R23 R25 = R_0402[[/\]]100K[[/\]]1%: Resistor 100kohm  1/16W 1% 0402; Part Number: R_0402; ManufacturerName: Yageo; ManufacturerPN: RC0402FR-07100KL; AlternativeManufacturer: Bourns Inc.; IsPreferred: 0; IsGeneric: 1; IngeniaID: 1454; TemperatureMaxC: 155; TemperatureMinC: -55; MTBF55h: 83317989; AlternativePN: CR0402-FX-1003GLF
R5#1 = R_0402[[/\]]220R[[/\]]1%,200mW: Resistor 220ohm 200mW high power; Part Number: R_0402; ManufacturerName: Panasonic Electronic Components; ManufacturerPN: ERJ-PA2F2200X; AlternativeManufacturer: VISHAY; IsPreferred: 0; IngeniaID: 3040; AlternativePN: CRCW0402220RFKEDHP; TemperatureMaxC: 155; TemperatureMinC: -55
R7#1 R1714 = AVR-M1005C180MTAAB: 18V varistor, 11Vworking, 16Apk 30Vclamp Varistor 0402; ManufacturerName: TDK Corporation; AlternativeManufacturer: Panasonic Electronic Components; IsPreferred: 1; IsGeneric: 0; IngeniaID: 4269; TemperatureMaxC: 125; TemperatureMinC: -40; AlternativePN: EZJ-P0V180HM
R8#1 R9#1 R10#1 R13#1 R17 = R_0402[[/\]]1K[[/\]]1%: RES 1K OHM 1/16W 1% 0402 SMD; Part Number: R_0402; ManufacturerName: Panasonic Electronic Components; ManufacturerPN: ERJ-2RKF1001X; AlternativeManufacturer: KOA Speer Electronics, Inc.; IsPreferred: 0; IsGeneric: 1; IngeniaID: 686; TemperatureMaxC: 155; TemperatureMinC: -55; MTBF55h: 91649788; AlternativePN: RK73H1ETTP1001F
R11#1 R22 = R_0402[[/\]]20K[[/\]]1%: RES 20K OHM 1/10W 1% 0402 SMD; Part Number: R_0402; ManufacturerName: Panasonic Electronic Components; ManufacturerPN: ERJ-2RKF2002X; AlternativeManufacturer: Vishay; IsPreferred: 0; IsGeneric: 1; IngeniaID: 688; TemperatureMaxC: 155; TemperatureMinC: -55; MTBF55h: 91649788; AlternativePN: CRCW040220K0FKED
R12#1 R20 = R_0402[[/\]]10K[[/\]]1%: RESISTOR 10K OHM 1/16W 1% 0402 SMD; Part Number: R_0402; ManufacturerName: Stackpole Electronics; ManufacturerPN: RMCF0402FT10K0; AlternativeManufacturer: Vishay Dale; IsPreferred: 0; IngeniaID: 685; IsGeneric: 1; MTBF55h: 91649788; TemperatureMaxC: 155; TemperatureMinC: -55; AlternativePN: CRCW040210K0FKED
R19 = R_0402[[/\]]1k65[[/\]]0.1%: Reistor 1k65 1.65kohm 1/16W 0.1%; Part Number: R_0402; ManufacturerName: TE connectivity; ManufacturerPN: CPF0402B1K65E1; AlternativeManufacturer: Yageo; IsPreferred: 0; IngeniaID: 2176; IsGeneric: 1; TemperatureMaxC: 155; TemperatureMinC: -55; AlternativePN: RT0402BRD071K65L
R21 = R_0402[[/\]]220k[[/\]]1%: RES 220k 1/16W 1% 0402; Part Number: R_0402; ManufacturerName: Vishay; ManufacturerPN: CRCW0402220KFKED; AlternativeManufacturer: Yageo; IsPreferred: 0; IsGeneric: 1; IngeniaID: 3480; TemperatureMaxC: 155; TemperatureMinC: -55; AlternativePN: AC0402FR-07220KL
R24 R26 = R_0402[[/\]]100k[[/\]]1%: Resistor 100kohm  1/16W 1% 0402; Part Number: R_0402; ManufacturerName: Yageo; ManufacturerPN: RC0402FR-07100KL; AlternativeManufacturer: Bourns Inc.; IsPreferred: 0; IsGeneric: 1; IngeniaID: 1454; TemperatureMaxC: 155; TemperatureMinC: -55; MTBF55h: 83317989; AlternativePN: CR0402-FX-1003GLF
RN2#1 RN5 = R_ARRAY_0804_8[[/\]]10K[[/\]]1%: Resistor array 4 x 10kohm 5% 0804; ManufacturerName: Vishay Dale; ManufacturerPN: CRA04S08310K0FTD; AlternativeManufacturer: Bourns; IsPreferred: 0; IngeniaID: 1290; IsGeneric: 1; TemperatureMaxC: 155; TemperatureMinC: -55; AlternativePN: CAT10-103J4LF
RN3#1 = R_ARRAY_0804_8[[/\]]15K[[/\]]5%: RESISTOR ARRAY4 15kohm 1/16W 5%; ManufacturerName: Panasonic; ManufacturerPN: EXB-28V153JX; AlternativeManufacturer: CTS Resistor Products; IsPreferred: 0; IngeniaID: 4270; TemperatureMaxC: 155; TemperatureMinC: -55; AlternativePN: 741C083153JP
RN4 = R_ARRAY_0804_8[[/\]]470R[[/\]]5%: RESISTOR ARRAY 470R 0804 5%; ManufacturerName: Bourns; ManufacturerPN: CAY10-471J4LF; AlternativeManufacturer: Panasonic; IsPreferred: 0; IsGeneric: 1; IngeniaID: 1940; TemperatureMaxC: 125; TemperatureMinC: -55; AlternativePN: EXB-28V471JX
RN6 = R_ARRAY_0804_8[[/\]]1K[[/\]]1%: RESISTOR ARRAY4 1k 1/16W 1%; ManufacturerName: Panasonic Electronic Components; ManufacturerPN: EXB-28V102JX; AlternativeManufacturer: Yageo; IsPreferred: 0; IngeniaID: 1502; IsGeneric: 1; TemperatureMaxC: 155; TemperatureMinC: -55; AlternativePN: YC124-JR-071KL; AdditionalInformation: 2nd alternative: RP104PJ102CS (Samsung Electro-Mechanics)
U1#1 = SN74LVC1G17DRYR: Buffer Non-Inverting 1.65V to 5.5V (Schmitt trigger Inputs 3.3V ready) 6VSON push-pull output; ManufacturerName: Texas Instruments; IsPreferred: 1; IsGeneric: 0; IngeniaID: 4427; TemperatureMaxC: 125; TemperatureMinC: -40
U2#1 = 74AHCT125BQ: Quad tristate buffer, 5V supply, 3.3V input, noninverting, 14-DHVQFN; ManufacturerName: Nexperia; ManufacturerPN: 74AHCT125BQ,115; IsPreferred: 0; IngeniaID: 4260; TemperatureMaxC: 125; TemperatureMinC: -40; AdditionalInformation: The alternative 74VHCT is 100% compatible; AlternativePN: 74VHCT125BQ,115
U3#1 = SN74LVC3G04YZPR: Triple inverter; ManufacturerName: Texas Instruments; IsPreferred: 0; IngeniaID: 4262; TemperatureMaxC: 125; TemperatureMinC: -40
U4 = NX5P3001UKZ: Bidirectional high-side power switch; ManufacturerName: NXP; IsPreferred: 0; IngeniaID: 4277; TemperatureMaxC: 125; TemperatureMinC: -40
U6 = FPF2495UCX: Load switch High Side P-Channel, Current Limiting adjustable, Overtemperature 150ºC Tjunction, Reverse current, UVLO; ManufacturerName: On semiconductor; IsPreferred: 1; IsGeneric: 0; IngeniaID: 4414; TemperatureMaxC: 150; TemperatureMinC: -40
